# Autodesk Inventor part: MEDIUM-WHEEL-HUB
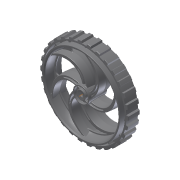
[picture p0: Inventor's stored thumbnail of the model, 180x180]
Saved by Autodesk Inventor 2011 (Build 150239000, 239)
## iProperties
Created: 2007-08
Part Number: MEDIUM-WHEEL-HUB
Material: ABS Plastic
Document SubType Name: Modeling
Density: 1.06 g/cm^3
Mass: 42.8255 g
Surface Area: 324.402 cm^2
Volume: 40.4014 cm^3
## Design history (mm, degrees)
feature "Base1"
workaxis "Work Axis1"
body "Solid1"
